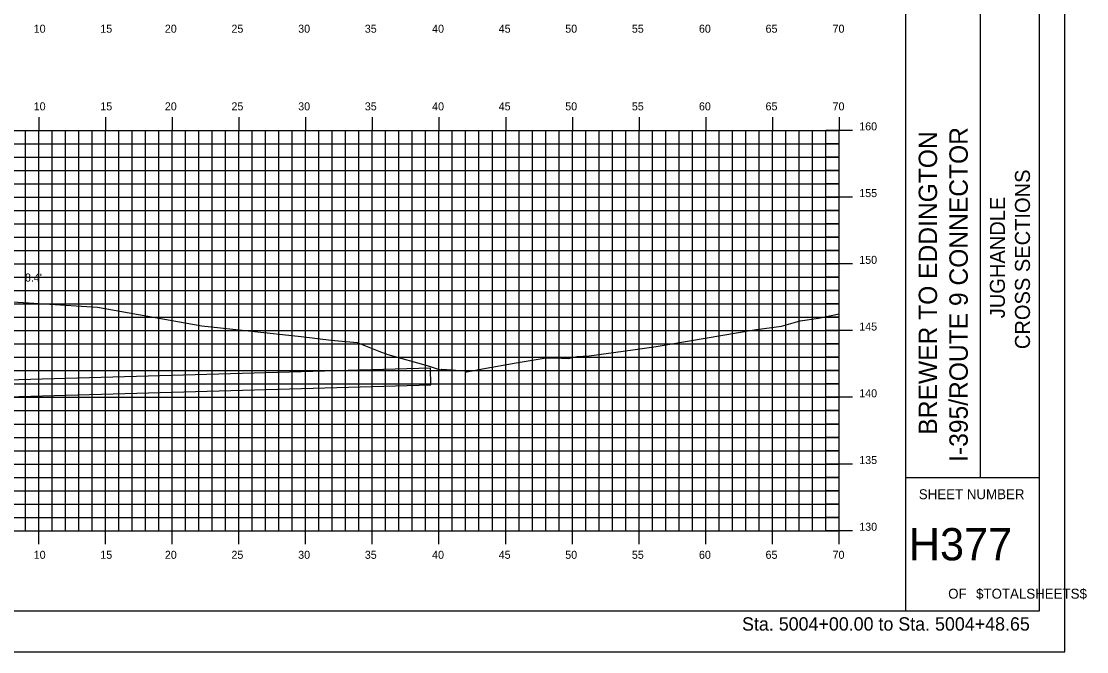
# Model space of a CAD drawing. Extents: x 852082 to 852254, y 365876 to 365986.
# Drawn here: x 852173.9 to 852253.7, y 365875.8 to 365923 of the extents above; entities that cross this region are included whole.
import ezdxf

# ---------------------------------------------------------------- set-up
doc = ezdxf.new("R2010")
doc.units = 0
for name, color, linetype in [('BORDER', 7, 'Continuous'), ('D_Drainage_Culvert', 7, 'Continuous'), ('D_Text_Standard', 7, 'Continuous'), ('H_V ANNOTATION', 7, 'Continuous'), ('MAJOR', 7, 'Continuous'), ('MINOR', 7, 'Continuous'), ('PLOT BOUNDARY', 7, 'Continuous'), ('S_Roadway_Centerline', 7, 'Continuous')]:
    doc.layers.add(name, color=color, linetype=linetype)

msp = doc.modelspace()

# ---------------------------------------------------------------- linework, layer by layer
at = {"layer": 'BORDER'}
for p, q in [((852240.168, 365878.833), (852240.168, 365983.833)), ((852245.759, 365888.836), (852245.759, 365923.836)), ((852240.168, 365888.836), (852250.168, 365888.836))]:
    msp.add_line(p, q, dxfattribs=at)
msp.add_lwpolyline([(852090.168, 365878.833), (852250.168, 365878.833), (852250.168, 365983.833), (852090.168, 365983.833)], close=True, dxfattribs=at)
at = {"layer": 'D_Drainage_Culvert'}
msp.add_lwpolyline([(852095.168, 365892.674), (852204.568, 365895.764), (852204.533, 365897.014), (852095.168, 365893.925)], dxfattribs=at)
at = {"layer": 'MAJOR'}
for p, q in [((852175.168, 365915.835), (852175.168, 365914.833)), ((852180.168, 365915.835), (852180.168, 365914.833)), ((852185.168, 365915.835), (852185.168, 365914.833)), ((852190.168, 365915.835), (852190.168, 365914.833)), ((852195.168, 365915.835), (852195.168, 365914.833)), ((852200.168, 365915.835), (852200.168, 365914.833)), ((852205.168, 365915.835), (852205.168, 365914.833)), ((852210.168, 365915.835), (852210.168, 365914.833)), ((852215.168, 365915.835), (852215.168, 365914.833)), ((852220.168, 365915.835), (852220.168, 365914.833)), ((852225.168, 365915.835), (852225.168, 365914.833)), ((852230.168, 365915.835), (852230.168, 365914.833)), ((852235.168, 365915.835), (852235.168, 365914.833)), ((852095.168, 365914.833), (852235.168, 365914.833)), ((852095.168, 365914.833), (852235.168, 365914.833)), ((852175.168, 365884.833), (852175.168, 365914.833)), ((852180.168, 365884.833), (852180.168, 365914.833)), ((852185.168, 365884.833), (852185.168, 365914.833)), ((852190.168, 365884.833), (852190.168, 365914.833)), ((852195.168, 365884.833), (852195.168, 365914.833)), ((852200.168, 365884.833), (852200.168, 365914.833)), ((852205.168, 365884.833), (852205.168, 365914.833)), ((852210.168, 365884.833), (852210.168, 365914.833)), ((852215.168, 365884.833), (852215.168, 365914.833)), ((852220.168, 365884.833), (852220.168, 365914.833)), ((852225.168, 365884.833), (852225.168, 365914.833)), ((852230.168, 365884.833), (852230.168, 365914.833)), ((852236.17, 365914.833), (852234.166, 365914.833)), ((852235.168, 365884.833), (852235.168, 365914.833)), ((852235.168, 365884.833), (852235.168, 365914.833)), ((852095.168, 365909.833), (852235.168, 365909.833)), ((852236.17, 365909.833), (852234.166, 365909.833)), ((852095.168, 365904.833), (852235.168, 365904.833)), ((852236.17, 365904.833), (852234.166, 365904.833)), ((852095.168, 365899.833), (852235.168, 365899.833)), ((852236.17, 365899.833), (852234.166, 365899.833)), ((852095.168, 365894.833), (852235.168, 365894.833)), ((852236.17, 365894.833), (852234.166, 365894.833)), ((852095.168, 365889.833), (852235.168, 365889.833)), ((852236.17, 365889.833), (852234.166, 365889.833)), ((852095.168, 365884.833), (852235.168, 365884.833)), ((852095.168, 365884.833), (852235.168, 365884.833)), ((852175.168, 365883.831), (852175.168, 365884.833)), ((852180.168, 365883.831), (852180.168, 365884.833)), ((852185.168, 365883.831), (852185.168, 365884.833)), ((852190.168, 365883.831), (852190.168, 365884.833)), ((852195.168, 365883.831), (852195.168, 365884.833)), ((852200.168, 365883.831), (852200.168, 365884.833)), ((852205.168, 365883.831), (852205.168, 365884.833)), ((852210.168, 365883.831), (852210.168, 365884.833)), ((852215.168, 365883.831), (852215.168, 365884.833)), ((852220.168, 365883.831), (852220.168, 365884.833)), ((852225.168, 365883.831), (852225.168, 365884.833)), ((852230.168, 365883.831), (852230.168, 365884.833)), ((852236.17, 365884.833), (852234.166, 365884.833)), ((852235.168, 365883.831), (852235.168, 365884.833))]:
    msp.add_line(p, q, dxfattribs=at)
at = {"layer": 'MINOR'}
for p, q in [((852174.168, 365884.833), (852174.168, 365914.833)), ((852176.168, 365884.833), (852176.168, 365914.833)), ((852177.168, 365884.833), (852177.168, 365914.833)), ((852178.168, 365884.833), (852178.168, 365914.833)), ((852179.168, 365884.833), (852179.168, 365914.833)), ((852181.168, 365884.833), (852181.168, 365914.833)), ((852182.168, 365884.833), (852182.168, 365914.833)), ((852183.168, 365884.833), (852183.168, 365914.833)), ((852184.168, 365884.833), (852184.168, 365914.833)), ((852186.168, 365884.833), (852186.168, 365914.833)), ((852187.168, 365884.833), (852187.168, 365914.833)), ((852188.168, 365884.833), (852188.168, 365914.833)), ((852189.168, 365884.833), (852189.168, 365914.833)), ((852191.168, 365884.833), (852191.168, 365914.833)), ((852192.168, 365884.833), (852192.168, 365914.833)), ((852193.168, 365884.833), (852193.168, 365914.833)), ((852194.168, 365884.833), (852194.168, 365914.833)), ((852196.168, 365884.833), (852196.168, 365914.833)), ((852197.168, 365884.833), (852197.168, 365914.833)), ((852198.168, 365884.833), (852198.168, 365914.833)), ((852199.168, 365884.833), (852199.168, 365914.833)), ((852201.168, 365884.833), (852201.168, 365914.833)), ((852202.168, 365884.833), (852202.168, 365914.833)), ((852203.168, 365884.833), (852203.168, 365914.833)), ((852204.168, 365884.833), (852204.168, 365914.833)), ((852206.168, 365884.833), (852206.168, 365914.833)), ((852207.168, 365884.833), (852207.168, 365914.833)), ((852208.168, 365884.833), (852208.168, 365914.833)), ((852209.168, 365884.833), (852209.168, 365914.833)), ((852211.168, 365884.833), (852211.168, 365914.833)), ((852212.168, 365884.833), (852212.168, 365914.833)), ((852213.168, 365884.833), (852213.168, 365914.833)), ((852214.168, 365884.833), (852214.168, 365914.833)), ((852216.168, 365884.833), (852216.168, 365914.833)), ((852217.168, 365884.833), (852217.168, 365914.833)), ((852218.168, 365884.833), (852218.168, 365914.833)), ((852219.168, 365884.833), (852219.168, 365914.833)), ((852221.168, 365884.833), (852221.168, 365914.833)), ((852222.168, 365884.833), (852222.168, 365914.833)), ((852223.168, 365884.833), (852223.168, 365914.833)), ((852224.168, 365884.833), (852224.168, 365914.833)), ((852226.168, 365884.833), (852226.168, 365914.833)), ((852227.168, 365884.833), (852227.168, 365914.833)), ((852228.168, 365884.833), (852228.168, 365914.833)), ((852229.168, 365884.833), (852229.168, 365914.833)), ((852231.168, 365884.833), (852231.168, 365914.833)), ((852232.168, 365884.833), (852232.168, 365914.833)), ((852233.168, 365884.833), (852233.168, 365914.833)), ((852234.168, 365884.833), (852234.168, 365914.833)), ((852095.168, 365913.833), (852235.168, 365913.833)), ((852235.168, 365913.833), (852234.166, 365913.833)), ((852095.168, 365912.833), (852235.168, 365912.833)), ((852235.168, 365912.833), (852234.166, 365912.833)), ((852095.168, 365911.833), (852235.168, 365911.833)), ((852235.168, 365911.833), (852234.166, 365911.833)), ((852095.168, 365910.833), (852235.168, 365910.833)), ((852235.168, 365910.833), (852234.166, 365910.833)), ((852095.168, 365908.833), (852235.168, 365908.833)), ((852235.168, 365908.833), (852234.166, 365908.833)), ((852095.168, 365907.833), (852235.168, 365907.833)), ((852235.168, 365907.833), (852234.166, 365907.833)), ((852095.168, 365906.833), (852235.168, 365906.833)), ((852235.168, 365906.833), (852234.166, 365906.833)), ((852095.168, 365905.833), (852235.168, 365905.833)), ((852235.168, 365905.833), (852234.166, 365905.833)), ((852095.168, 365903.833), (852235.168, 365903.833)), ((852235.168, 365903.833), (852234.166, 365903.833)), ((852095.168, 365902.833), (852235.168, 365902.833)), ((852235.168, 365902.833), (852234.166, 365902.833)), ((852095.168, 365901.833), (852235.168, 365901.833)), ((852235.168, 365901.833), (852234.166, 365901.833)), ((852095.168, 365900.833), (852235.168, 365900.833)), ((852235.168, 365900.833), (852234.166, 365900.833)), ((852095.168, 365898.833), (852235.168, 365898.833)), ((852235.168, 365898.833), (852234.166, 365898.833)), ((852095.168, 365897.833), (852235.168, 365897.833)), ((852235.168, 365897.833), (852234.166, 365897.833)), ((852095.168, 365896.833), (852235.168, 365896.833)), ((852235.168, 365896.833), (852234.166, 365896.833)), ((852095.168, 365895.833), (852235.168, 365895.833)), ((852235.168, 365895.833), (852234.166, 365895.833)), ((852095.168, 365893.833), (852235.168, 365893.833)), ((852235.168, 365893.833), (852234.166, 365893.833)), ((852095.168, 365892.833), (852235.168, 365892.833)), ((852235.168, 365892.833), (852234.166, 365892.833)), ((852095.168, 365891.833), (852235.168, 365891.833)), ((852235.168, 365891.833), (852234.166, 365891.833)), ((852095.168, 365890.833), (852235.168, 365890.833)), ((852235.168, 365890.833), (852234.166, 365890.833)), ((852095.168, 365888.833), (852235.168, 365888.833)), ((852235.168, 365888.833), (852234.166, 365888.833)), ((852095.168, 365887.833), (852235.168, 365887.833)), ((852235.168, 365887.833), (852234.166, 365887.833)), ((852095.168, 365886.833), (852235.168, 365886.833)), ((852235.168, 365886.833), (852234.166, 365886.833)), ((852095.168, 365885.833), (852235.168, 365885.833)), ((852235.168, 365885.833), (852234.166, 365885.833))]:
    msp.add_line(p, q, dxfattribs=at)
at = {"layer": 'PLOT BOUNDARY'}
msp.add_lwpolyline([(852082.075, 365875.774), (852252.075, 365875.774), (852252.075, 365985.774), (852082.075, 365985.774)], close=True, dxfattribs=at)
at = {"layer": 'S_Roadway_Centerline'}
msp.add_lwpolyline([(852167.58, 365902.33), (852175.592, 365901.847), (852179.585, 365901.585), (852187.402, 365900.186), (852194.837, 365899.4), (852197.098, 365899.107), (852199.033, 365898.933), (852200.658, 365898.302), (852201.338, 365898.031), (852204.364, 365897.18), (852205.26, 365896.88), (852205.375, 365896.95), (852207.141, 365896.821), (852207.268, 365896.749), (852208.429, 365896.974), (852210.955, 365897.422), (852213.215, 365897.792), (852213.81, 365897.8), (852214.877, 365897.736), (852215.494, 365897.891), (852216.436, 365897.929), (852219.707, 365898.393), (852221.438, 365898.639), (852228.789, 365899.897), (852230.85, 365900.175), (852232.238, 365900.574), (852233.609, 365900.773), (852235.168, 365901.078)], dxfattribs=at)

# ---------------------------------------------------------------- texts
at = {"layer": 'BORDER'}
for s, height, p in [('BREWER TO EDDINGTON', 1.37787, (852242.502, 365892.038)), ('I-395/ROUTE 9 CONNECTOR', 1.37787, (852244.803, 365889.998)), ('CROSS SECTIONS', 1.125, (852249.466, 365898.444)), ('JUGHANDLE', 1.125, (852247.587, 365900.756))]:
    msp.add_text(s, height=height, rotation=90, dxfattribs=at).set_placement(p)
for s, height, p in [('SHEET NUMBER', 0.74527, (852241.134, 365887.2)), ('H377', 2.4194, (852240.388, 365882.616)), ('OF', 0.7453, (852243.335, 365879.746)), ('$TOTALSHEETS$', 0.74527, (852245.425, 365879.746))]:
    msp.add_text(s, height=height, dxfattribs=at).set_placement(p)
at = {"layer": 'D_Text_Standard'}
msp.add_text("8.4'", height=0.6, dxfattribs=at).set_placement((852174.134, 365903.508))
at = {"layer": 'H_V ANNOTATION'}
for s, height, p in [('10', 0.6, (852174.793, 365922.151)), ('15', 0.6, (852179.785, 365922.151)), ('20', 0.6, (852184.622, 365922.151)), ('25', 0.6, (852189.614, 365922.151)), ('30', 0.6, (852194.617, 365922.151)), ('35', 0.6, (852199.609, 365922.151)), ('40', 0.6, (852204.654, 365922.151)), ('45', 0.6, (852209.646, 365922.151)), ('50', 0.6, (852214.633, 365922.151)), ('55', 0.6, (852219.625, 365922.151)), ('60', 0.6, (852224.654, 365922.151)), ('65', 0.6, (852229.646, 365922.151)), ('70', 0.6, (852234.67, 365922.151)), ('10', 0.6, (852174.793, 365916.333)), ('15', 0.6, (852179.785, 365916.333)), ('20', 0.6, (852184.622, 365916.333)), ('25', 0.6, (852189.614, 365916.333)), ('30', 0.6, (852194.617, 365916.333)), ('35', 0.6, (852199.609, 365916.333)), ('40', 0.6, (852204.654, 365916.333)), ('45', 0.6, (852209.646, 365916.333)), ('50', 0.6, (852214.633, 365916.333)), ('55', 0.6, (852219.625, 365916.333)), ('60', 0.6, (852224.654, 365916.333)), ('65', 0.6, (852229.646, 365916.333)), ('70', 0.6, (852234.67, 365916.333)), ('160', 0.6, (852236.668, 365914.833)), ('155', 0.6, (852236.668, 365909.833)), ('150', 0.6, (852236.668, 365904.833)), ('145', 0.6, (852236.668, 365899.833)), ('140', 0.6, (852236.668, 365894.833)), ('135', 0.6, (852236.668, 365889.833)), ('130', 0.6, (852236.668, 365884.833)), ('10', 0.6, (852174.793, 365882.733)), ('15', 0.6, (852179.785, 365882.733)), ('20', 0.6, (852184.622, 365882.733)), ('25', 0.6, (852189.614, 365882.733)), ('30', 0.6, (852194.617, 365882.733)), ('35', 0.6, (852199.609, 365882.733)), ('40', 0.6, (852204.654, 365882.733)), ('45', 0.6, (852209.646, 365882.733)), ('50', 0.6, (852214.633, 365882.733)), ('55', 0.6, (852219.625, 365882.733)), ('60', 0.6, (852224.654, 365882.733)), ('65', 0.6, (852229.646, 365882.733)), ('70', 0.6, (852234.67, 365882.733)), ('Sta. 5004+00.00 to Sta. 5004+48.65', 1.0002, (852227.885, 365877.353))]:
    msp.add_text(s, height=height, dxfattribs=at).set_placement(p)

doc.saveas('drawing.dxf')
